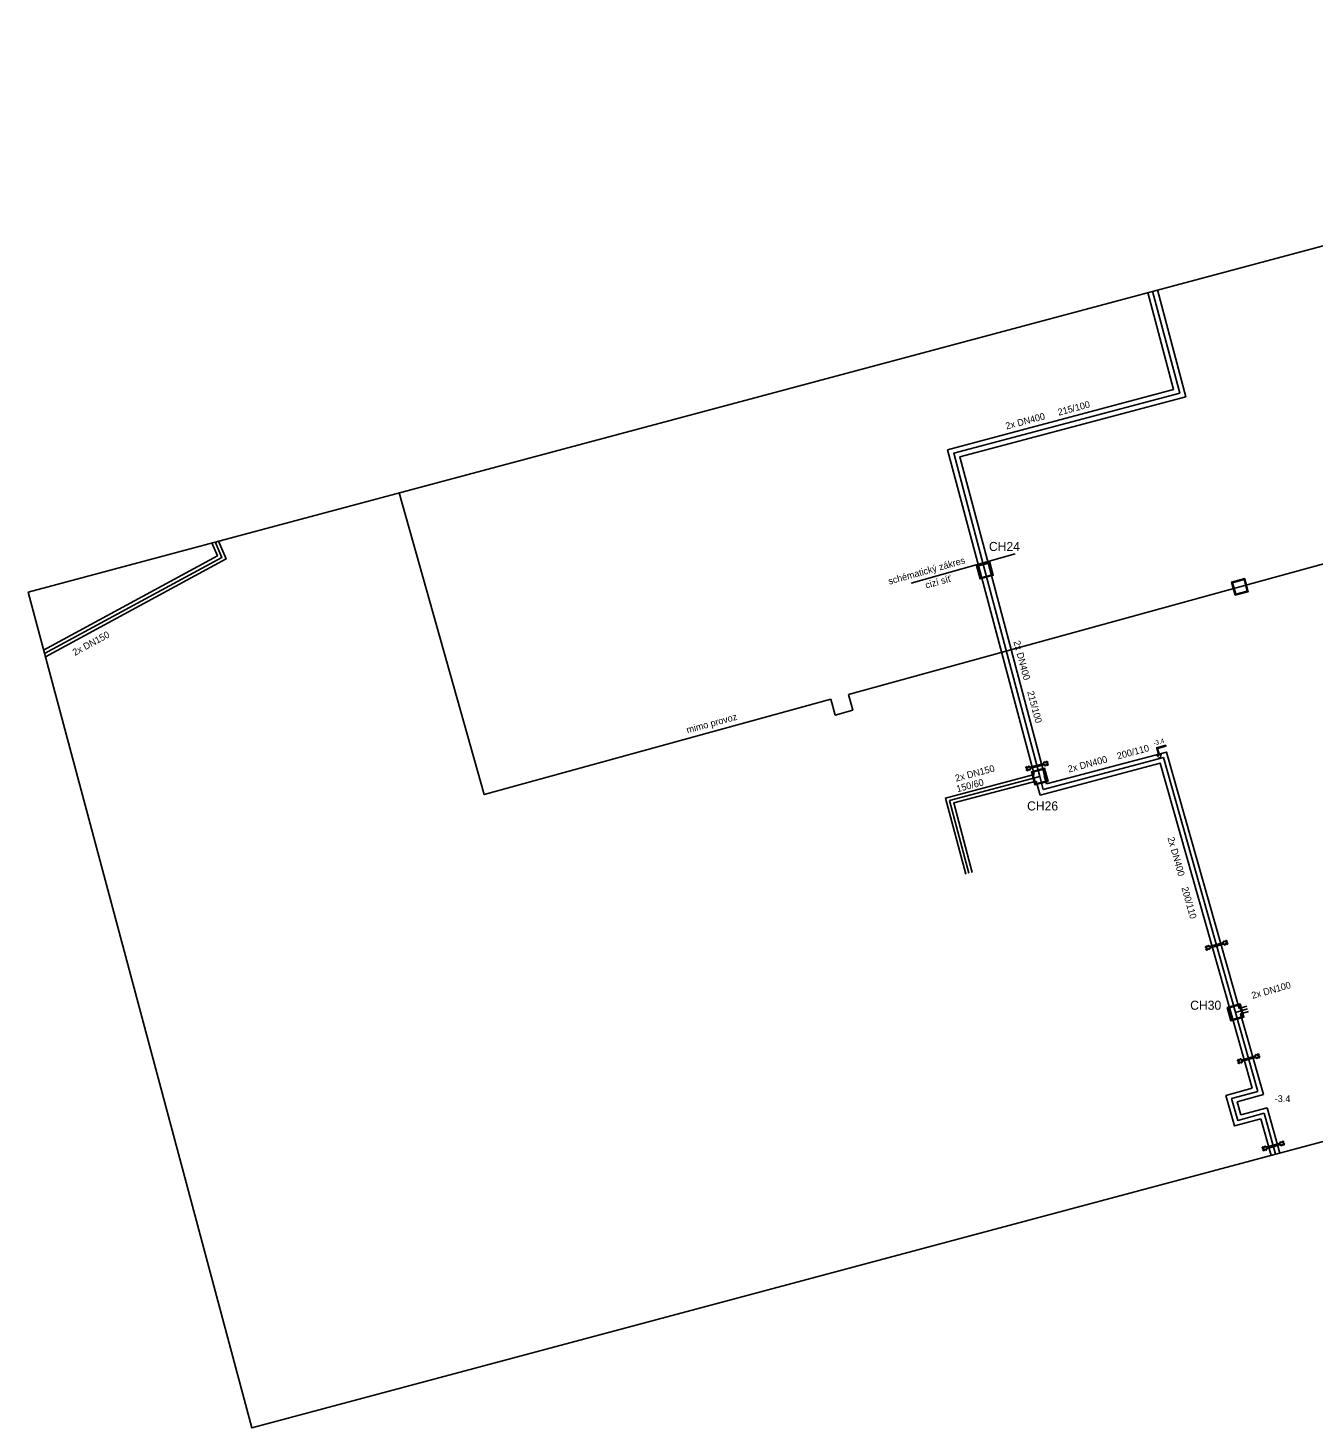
# Model space of a CAD drawing. Extents: x -599341 to -598827, y -1159084 to -1158776.
# Drawn here: x -599341.2 to -599057.8, y -1159084.3 to -1158775.6 of the extents above; entities that cross this region are included whole.
import ezdxf

# ---------------------------------------------------------------- set-up
doc = ezdxf.new("R2010")
doc.units = 0
for name, color, linetype in [('Horkovod - trasa - okraj', 7, 'Continuous'), ('Horkovod - trasa popis', 7, 'Continuous'), ('Horkovod - trasa popis 2', 7, 'Continuous'), ('Horkovod - trasa popis 3', 7, 'Continuous'), ('Level 46', 7, 'Continuous'), ('Osa trasy horkovodu', 7, 'Continuous'), ('Osa trasy parovodu', 7, 'Continuous'), ('Osa trasy teplovodu', 7, 'Continuous'), ('označení', 7, 'Continuous'), ('Parovod - trasa popis', 7, 'Continuous'), ('Pevný bod trasy horkovodu', 7, 'Continuous'), ('Teplovod - trasa popis', 7, 'Continuous'), ('Teplovod - trasa popis 2', 7, 'Continuous'), ('výška krytí', 7, 'Continuous'), ('Výšková kóta trasy horkovodu', 7, 'Continuous'), ('Šachta trasy horkovodu', 7, 'Continuous'), ('Šachta trasy parovodu', 7, 'Continuous')]:
    doc.layers.add(name, color=color, linetype=linetype)

msp = doc.modelspace()

# ---------------------------------------------------------------- linework, layer by layer
at = {"layer": 'Horkovod - trasa - okraj'}
for p, q in [((-599129.23, -1158894.94), (-599117.14, -1158940.37)), ((-599119.46, -1158940.21), (-599131.35, -1158895.5)), ((-599117.23, -1158940.4), (-599116.73, -1158942.29)), ((-599118.15, -1158944.74), (-599118.97, -1158941.64)), ((-599076.03, -1158992.92), (-599071.37, -1159009.38)), ((-599074.27, -1158991.8), (-599072.55, -1158991.31)), ((-599072.22, -1158992.46), (-599073.94, -1158992.95)), ((-599073.94, -1158992.95), (-599068.9, -1159010.78)), ((-599068.08, -1159013.67), (-599065.25, -1159023.67)), ((-599069.47, -1159016.12), (-599067.19, -1159024.18))]:
    msp.add_line(p, q, dxfattribs=at)
for points in [[(-599092.27, -1158833.36), (-599086.01, -1158856.89), (-599135.83, -1158870.15), (-599129.23, -1158894.94)], [(-599131.35, -1158895.5), (-599138.52, -1158868.58), (-599088.7, -1158855.33), (-599094.39, -1158833.93)], [(-599300.69, -1158889.11), (-599299.47, -1158891.98), (-599337.81, -1158912.77)], [(-599299.23, -1158888.72), (-599297.56, -1158892.65), (-599337.42, -1158914.26)], [(-599116.73, -1158942.29), (-599090.27, -1158935.25), (-599074.27, -1158991.8)], [(-599118.15, -1158944.74), (-599091.65, -1158937.69), (-599076.03, -1158992.92)], [(-599119.46, -1158940.21), (-599139, -1158945.41), (-599134.53, -1158962.18)], [(-599118.97, -1158941.64), (-599137.16, -1158946.48), (-599133.08, -1158961.79)], [(-599071.37, -1159009.38), (-599077.17, -1159010.95), (-599075.26, -1159017.68), (-599069.47, -1159016.12)], [(-599068.9, -1159010.78), (-599074.69, -1159012.35), (-599073.87, -1159015.24), (-599068.08, -1159013.67)]]:
    msp.add_lwpolyline(points, dxfattribs=at)
at = {"layer": 'Level 46'}
msp.add_lwpolyline([(-599341.24, -1158899.96), (-598876.32, -1158775.6), (-598827.01, -1158959.94), (-599291.93, -1159084.3)], close=True, dxfattribs=at)
msp.add_lwpolyline([(-599341.24, -1158899.96), (-598876.32, -1158775.6), (-598827.01, -1158959.94), (-599291.93, -1159084.3)], close=True, dxfattribs=at)
at = {"layer": 'Osa trasy horkovodu'}
for p, q in [((-599130.29, -1158895.22), (-599118.2, -1158940.66)), ((-599118.2, -1158940.66), (-599117.44, -1158943.51)), ((-599075.07, -1158992.65), (-599072.38, -1158991.89)), ((-599075.07, -1158992.65), (-599070.14, -1159010.08)), ((-599068.77, -1159014.89), (-599066.22, -1159023.92))]:
    msp.add_line(p, q, dxfattribs=at)
for points in [[(-599093.33, -1158833.65), (-599087.35, -1158856.11), (-599137.17, -1158869.36), (-599130.29, -1158895.22)], [(-599299.96, -1158888.92), (-599298.51, -1158892.32), (-599337.61, -1158913.51)], [(-599117.44, -1158943.51), (-599090.96, -1158936.47), (-599075.07, -1158992.65)], [(-599118.2, -1158940.66), (-599138.08, -1158945.95), (-599133.81, -1158961.99)], [(-599070.14, -1159010.08), (-599075.93, -1159011.65), (-599074.57, -1159016.46), (-599068.77, -1159014.89)]]:
    msp.add_lwpolyline(points, dxfattribs=at)
at = {"layer": 'Osa trasy parovodu'}
for p, q in [((-599050.49, -1158892.36), (-599074.08, -1158898.85)), ((-599074.08, -1158898.85), (-599160.39, -1158922.56))]:
    msp.add_line(p, q, dxfattribs=at)
for points in [[(-599164.25, -1158923.62), (-599240.68, -1158944.62), (-599259.43, -1158878.08)], [(-599160.39, -1158922.56), (-599159.44, -1158926.03), (-599163.29, -1158927.09), (-599164.25, -1158923.62)]]:
    msp.add_lwpolyline(points, dxfattribs=at)
at = {"layer": 'Osa trasy teplovodu'}
msp.add_lwpolyline([(-599146.55, -1158897.99), (-599123.66, -1158891.56)], dxfattribs=at)
at = {"layer": 'Pevný bod trasy horkovodu'}
for points in [[(-599117.22, -1158937.75), (-599117.38, -1158937.66), (-599117.38, -1158937.66), (-599117.2, -1158937.42), (-599116.88, -1158937.6), (-599116.69, -1158937.28), (-599116.69, -1158937.28), (-599116.46, -1158937.46), (-599116.63, -1158937.75), (-599116.33, -1158937.92), (-599116.46, -1158938.19), (-599116.77, -1158938.01), (-599116.96, -1158938.32), (-599117.23, -1158938.2), (-599117.14, -1158938.05), (-599120.36, -1158938.91), (-599120.26, -1158938.97), (-599120.39, -1158939.24), (-599120.7, -1158939.05), (-599120.89, -1158939.37), (-599121.16, -1158939.25), (-599120.96, -1158938.91), (-599121.31, -1158938.71), (-599121.31, -1158938.7), (-599121.13, -1158938.47), (-599120.81, -1158938.65), (-599120.62, -1158938.33), (-599120.62, -1158938.33), (-599120.39, -1158938.51), (-599120.45, -1158938.61), (-599117.22, -1158937.75)], [(-599077.66, -1158977.25), (-599077.82, -1158977.16), (-599077.82, -1158977.16), (-599077.65, -1158976.92), (-599077.32, -1158977.1), (-599077.14, -1158976.77), (-599077.14, -1158976.77), (-599076.9, -1158976.95), (-599077.07, -1158977.24), (-599076.77, -1158977.41), (-599076.89, -1158977.68), (-599077.21, -1158977.5), (-599077.39, -1158977.82), (-599077.66, -1158977.7), (-599077.58, -1158977.55), (-599080.79, -1158978.46), (-599080.68, -1158978.52), (-599080.81, -1158978.78), (-599081.13, -1158978.61), (-599081.3, -1158978.92), (-599081.58, -1158978.81), (-599081.38, -1158978.46), (-599081.73, -1158978.27), (-599081.73, -1158978.26), (-599081.56, -1158978.03), (-599081.24, -1158978.21), (-599081.06, -1158977.88), (-599081.05, -1158977.88), (-599080.82, -1158978.05), (-599080.88, -1158978.16), (-599077.66, -1158977.25)], [(-599070.58, -1159002.26), (-599070.74, -1159002.17), (-599070.75, -1159002.17), (-599070.57, -1159001.93), (-599070.25, -1159002.11), (-599070.07, -1159001.78), (-599070.06, -1159001.78), (-599069.83, -1159001.96), (-599069.99, -1159002.25), (-599069.7, -1159002.42), (-599069.82, -1159002.69), (-599070.14, -1159002.51), (-599070.31, -1159002.83), (-599070.59, -1159002.71), (-599070.5, -1159002.56), (-599073.71, -1159003.47), (-599073.61, -1159003.53), (-599073.73, -1159003.79), (-599074.05, -1159003.62), (-599074.23, -1159003.93), (-599074.5, -1159003.82), (-599074.31, -1159003.47), (-599074.66, -1159003.28), (-599074.66, -1159003.27), (-599074.49, -1159003.04), (-599074.17, -1159003.21), (-599073.98, -1159002.89), (-599073.98, -1159002.89), (-599073.74, -1159003.06), (-599073.8, -1159003.17), (-599070.58, -1159002.26)], [(-599065.14, -1159021.5), (-599065.3, -1159021.41), (-599065.3, -1159021.41), (-599065.13, -1159021.17), (-599064.81, -1159021.35), (-599064.62, -1159021.03), (-599064.62, -1159021.02), (-599064.38, -1159021.2), (-599064.55, -1159021.5), (-599064.25, -1159021.66), (-599064.38, -1159021.93), (-599064.69, -1159021.75), (-599064.87, -1159022.07), (-599065.14, -1159021.95), (-599065.06, -1159021.8), (-599068.27, -1159022.71), (-599068.17, -1159022.77), (-599068.29, -1159023.04), (-599068.61, -1159022.86), (-599068.79, -1159023.18), (-599069.06, -1159023.06), (-599068.86, -1159022.72), (-599069.21, -1159022.52), (-599069.22, -1159022.52), (-599069.04, -1159022.28), (-599068.72, -1159022.46), (-599068.54, -1159022.13), (-599068.53, -1159022.13), (-599068.3, -1159022.31), (-599068.36, -1159022.41), (-599065.14, -1159021.5)]]:
    msp.add_lwpolyline(points, dxfattribs=at)
at = {"layer": 'Výšková kóta trasy horkovodu'}
msp.add_lwpolyline([(-599091.84, -1158935.91), (-599091.46, -1158935.8), (-599091.69, -1158936.68), (-599092.36, -1158936.06), (-599091.99, -1158935.95), (-599092.42, -1158934.42), (-599092.42, -1158934.42), (-599092.45, -1158934.32), (-599090.44, -1158933.76), (-599090.4, -1158933.92), (-599092.25, -1158934.45), (-599091.84, -1158935.91)], dxfattribs=at)
at = {"layer": 'Šachta trasy horkovodu'}
for points in [[(-599132.13, -1158894.15), (-599129.22, -1158893.38), (-599128.45, -1158896.28), (-599131.35, -1158897.06), (-599132.13, -1158894.15)], [(-599131.22, -1158896.83), (-599128.68, -1158896.15), (-599129.36, -1158893.61), (-599131.9, -1158894.29), (-599131.22, -1158896.83)], [(-599120.04, -1158939.59), (-599117.13, -1158938.81), (-599116.36, -1158941.72), (-599119.26, -1158942.49), (-599120.04, -1158939.59)], [(-599119.13, -1158942.26), (-599116.59, -1158941.59), (-599117.27, -1158939.04), (-599119.81, -1158939.72), (-599119.13, -1158942.26)], [(-599076.92, -1158991.61), (-599074.03, -1158990.79), (-599073.21, -1158993.68), (-599076.1, -1158994.5), (-599076.92, -1158991.61)], [(-599075.97, -1158994.27), (-599073.44, -1158993.55), (-599074.16, -1158991.02), (-599076.69, -1158991.74), (-599075.97, -1158994.27)]]:
    msp.add_lwpolyline(points, dxfattribs=at)
at = {"layer": 'Šachta trasy parovodu'}
for points in [[(-599075.13, -1158900.69), (-599075.93, -1158897.79), (-599073.03, -1158897), (-599072.23, -1158899.89), (-599075.13, -1158900.69)], [(-599072.46, -1158899.76), (-599073.16, -1158897.23), (-599075.7, -1158897.92), (-599075, -1158900.46), (-599072.46, -1158899.76)]]:
    msp.add_lwpolyline(points, dxfattribs=at)

# ---------------------------------------------------------------- texts
at = {"layer": 'Horkovod - trasa popis'}
for s, rotation, p in [('2x DN400', 14.9034, (-599125.54, -1158864.14)), ('2x DN150', 28.476, (-599330.93, -1158914.07)), ('2x DN400', 284.9319, (-599124.02, -1158910.9)), ('2x DN150', 14.905, (-599136.64, -1158941.79)), ('2x DN400', 14.8969, (-599111.8, -1158939.78)), ('2x DN400', 285.7913, (-599090.06, -1158954.18)), ('2x DN100', 15.7902, (-599071.3, -1158989.69))]:
    msp.add_text(s, height=1.5, rotation=rotation, dxfattribs=at).set_placement(p)
at = {"layer": 'Horkovod - trasa popis 2'}
for s, rotation, p in [('215/100', 14.9034, (-599114.02, -1158861.09)), ('215/100', 284.9028, (-599120.99, -1158921.98)), ('200/110', 14.9045, (-599100.97, -1158936.88)), ('150/60', 14.905, (-599136.36, -1158944.13)), ('200/110', 285.7947, (-599086.99, -1158965.19))]:
    msp.add_text(s, height=1.5, rotation=rotation, dxfattribs=at).set_placement(p)
at = {"layer": 'Horkovod - trasa popis 3'}
msp.add_text('-3.4', height=1.5, dxfattribs=at).set_placement((-599066.42, -1159012.43))
at = {"layer": 'označení'}
for s, p in [('CH24', (-599129.41, -1158890.92)), ('CH26', (-599121, -1158948.13)), ('CH30', (-599085.05, -1158992.08))]:
    msp.add_text(s, height=2, dxfattribs=at).set_placement(p)
at = {"layer": 'Parovod - trasa popis'}
msp.add_text('mimo provoz', height=1.5, rotation=15.3553, dxfattribs=at).set_placement((-599195.87, -1158931.14))
at = {"layer": 'Teplovod - trasa popis'}
msp.add_text('cizí síť', height=1.5, rotation=15.708, dxfattribs=at).set_placement((-599143.22, -1158899.21))
at = {"layer": 'Teplovod - trasa popis 2'}
msp.add_text('schématický zákres', height=1.5, rotation=15.708, dxfattribs=at).set_placement((-599151.37, -1158898.35))
at = {"layer": 'výška krytí'}
msp.add_text('-3.4', height=1, rotation=15.8136, dxfattribs=at).set_placement((-599092.97, -1158933.82))

doc.saveas('drawing.dxf')
